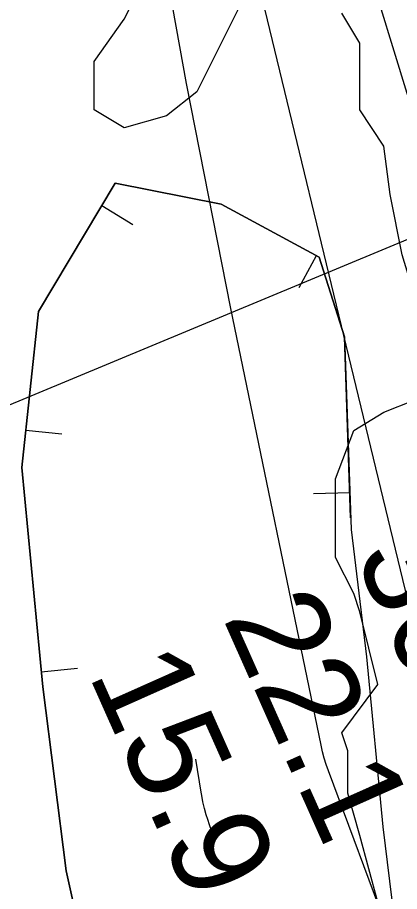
# Model space of a CAD drawing. Extents: x 3405885 to 3443815, y 558517 to 583997.
# Drawn here: x 3413949 to 3414211, y 574766 to 575366 of the extents above; entities that cross this region are included whole.
import ezdxf

# ---------------------------------------------------------------- set-up
doc = ezdxf.new("R2010")
doc.units = 0
for name, color, linetype in [('V-BORW-LINE', 7, 'Continuous'), ('V-RIVR-RANG', 7, 'Continuous'), ('V-SITE-VEGE', 7, 'Continuous'), ('V-TOPO-MAJR', 7, 'Continuous'), ('V-TOPO-MINR', 7, 'Continuous')]:
    doc.layers.add(name, color=color, linetype=linetype)

msp = doc.modelspace()

# ---------------------------------------------------------------- linework, layer by layer
at = {"layer": 'V-BORW-LINE'}
for p, q in [((3414006.68, 575236.42), (3414028.12, 575223.57)), ((3414154.1, 575202.01), (3414142.19, 575180.02)), ((3413954.54, 575082.31), (3413979.4, 575079.68)), ((3414177.06, 575039.32), (3414152.08, 575038.49)), ((3413965.21, 574916.5), (3413990.09, 574918.88))]:
    msp.add_line(p, q, dxfattribs=at)
for points in [[(3414020.48, 574607.8), (3413982.33, 574779.78), (3413966.2, 574906.13), (3413951.8, 575056.58), (3413963.19, 575163.86), (3414015.98, 575251.93), (3414088.78, 575237.36), (3414155.98, 575200.99), (3414173.47, 575146.37), (3414177.91, 575014.03), (3414188.62, 574926.67), (3414199.86, 574810.07), (3414210.47, 574722.32)], [(3414177.64, 575022.22), (3414173.47, 575146.37), (3414155.98, 575200.99), (3414088.78, 575237.36), (3414015.98, 575251.93), (3413963.19, 575163.86), (3413951.8, 575056.58), (3413966.2, 574906.13), (3413982.33, 574779.78), (3414020.48, 574607.8), (3414064.2, 574496.78), (3414128.97, 574382.61), (3414186.3, 574281.56), (3414238.27, 574184.85), (3414294.44, 574067.73), (3414337.48, 573960.17), (3414386.34, 573865.56), (3414442.89, 573781.72), (3414484.52, 573746.28)]]:
    msp.add_lwpolyline(points, dxfattribs=at)
at = {"layer": 'V-RIVR-RANG'}
msp.add_line((3413794.97, 575038.07), (3415069.36, 575567.51), dxfattribs=at)
at = {"layer": 'V-SITE-VEGE'}
for points in [[(3414101, 575372.76), (3414071.96, 575314.64), (3414051.22, 575298.04), (3414022.18, 575289.74), (3414001.44, 575302.19), (3414001.44, 575335.4), (3414022.18, 575364.46), (3414038.77, 575397.67)], [(3414196.4, 574758.37), (3414183.96, 574804.03), (3414175.66, 574833.09), (3414175.66, 574862.15), (3414171.51, 574874.6), (3414196.4, 574907.82), (3414183.96, 574957.63), (3414179.81, 574970.08), (3414167.37, 574994.99), (3414167.37, 575048.96), (3414179.81, 575082.17), (3414200.55, 575094.62), (3414221.29, 575102.93), (3414229.59, 575123.68), (3414229.59, 575148.59), (3414212.99, 575202.56), (3414204.7, 575244.07), (3414200.55, 575277.28), (3414183.96, 575302.19), (3414183.96, 575347.86), (3414171.51, 575368.61)]]:
    msp.add_lwpolyline(points, dxfattribs=at)
at = {"layer": 'V-TOPO-MAJR'}
for points in [[(3414133.11, 575584.44), (3414326.99, 574953.09), (3414329.92, 574943.99), (3414333.02, 574934.95), (3414336.37, 574926), (3414339.89, 574917.11), (3414623.77, 574227.81)], [(3414397.02, 574473.45), (3414244.39, 574866.56), (3414239.9, 574878.85), (3414235.74, 574891.25), (3414232.08, 574903.8), (3414228.75, 574916.45), (3414069.77, 575574.3)]]:
    msp.add_lwpolyline(points, dxfattribs=at)
at = {"layer": 'V-TOPO-MINR'}
for points in [[(3414302.04, 574473.15), (3414162.43, 574848.51), (3414160.94, 574852.81), (3414159.59, 574857.15), (3414158.43, 574861.54), (3414157.41, 574865.97), (3414095.3, 575165.73), (3414065.04, 575320.36), (3414037.08, 575475.38)], [(3414083.37, 574803.56), (3414082.12, 574807.42), (3414080.84, 574811.27), (3414079.54, 574815.1), (3414078.46, 574818.35), (3414077.22, 574822.67), (3414076.21, 574827.06), (3414075.36, 574831.48), (3414074.99, 574833.7), (3414071.4, 574856.53)]]:
    msp.add_lwpolyline(points, dxfattribs=at)

# ---------------------------------------------------------------- texts
at = {"layer": 'V-RIVR-RANG'}
for s, p in [('30.3', (3414179.9, 574996.5)), ('22.1', (3414089.62, 574953.4)), ('15.9', (3413997.31, 574914.89))]:
    msp.add_text(s, height=67, rotation=294.01833, dxfattribs=at).set_placement(p)

doc.saveas('drawing.dxf')
